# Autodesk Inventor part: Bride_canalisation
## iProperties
Shininess: 64.0
Length Units: 11269
Angle Units: 11279
Time Units: 11290
Mass Units: 11283
Length Display Precision: 3
Angle Display Precision: 2
Compacted: True
Part Number: Bride_canalisation
Document SubType Name: Modeling
Created: 2008-02
Material: Acier inoxydable, austénitique
Designer: Pascal
Density: 0.0
Volumn: 0.0
Area: 0.0
PropertySet Name: Model Information
Control State: 0
Master: False
Checked Out: False
DESIGNATION: pièce
Author: Pascal
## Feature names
1. Extrusion1
2. Extrusion2
3. Réseau rectangulaire1 [Rectangular Pattern]
4. Extrusion3
5. Réseau rectangulaire2 [Rectangular Pattern]
